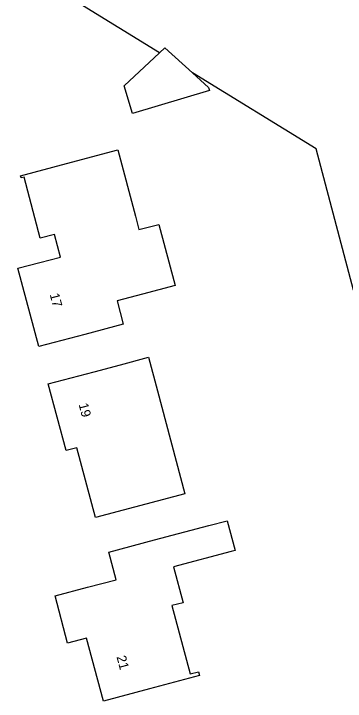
# Model space of a CAD drawing. Extents: x 162157 to 163165, y 378998 to 380775.
# Drawn here: x 162635.7 to 162670.5, y 380607.6 to 380679.9 of the extents above; entities that cross this region are included whole.
import ezdxf

# ---------------------------------------------------------------- set-up
doc = ezdxf.new("R2010")
doc.units = 0
for name, color, linetype in [('IMGEO_Berm_groen', 7, 'Continuous'), ('IMGEO_Gemengd_bos', 7, 'Continuous'), ('IMGEO_Pand', 7, 'Continuous'), ('IMGEO_Pand_nummerreeks', 7, 'Continuous')]:
    doc.layers.add(name, color=color, linetype=linetype)

msp = doc.modelspace()

# ---------------------------------------------------------------- linework, layer by layer
at = {"layer": 'IMGEO_Berm_groen'}
msp.add_arc((162610.535, 380570.327), 42.385, 51.06189, 64.46568, dxfattribs=at)
at = {"layer": 'IMGEO_Gemengd_bos'}
for points in [[(162651.018, 380675.815), (162622.41, 380693.42)], [(162686.842, 380455.383), (162698.747, 380463.798), (162717.329, 380476.675), (162717.214, 380477.109), (162722.756, 380480.815), (162721.635, 380488.635), (162709.746, 380529.126), (162706.597, 380543.52), (162702.968, 380557.567), (162695.09, 380585.37), (162687.837, 380613.552), (162683.878, 380612.514), (162673.502, 380651.377), (162671.402, 380650.811), (162667.467, 380665.693), (162654.457, 380673.698)]]:
    msp.add_lwpolyline(points, dxfattribs=at)
at = {"layer": 'IMGEO_Pand'}
for points in [[(162654.457, 380673.698), (162656.161, 380672.161), (162656.258, 380671.836), (162648.157, 380669.426), (162647.289, 380672.347), (162651.018, 380675.815)], [(162651.018, 380675.815), (162651.557, 380676.316), (162654.457, 380673.698)], [(162638.303, 380644.893), (162636.116, 380653.142), (162638.41, 380653.75), (162640.591, 380654.31), (162639.959, 380656.696), (162638.476, 380656.304), (162636.771, 380662.734), (162636.462, 380662.652), (162636.403, 380662.875), (162641.237, 380664.156), (162646.619, 380665.583), (162648.468, 380658.606), (162648.843, 380657.193), (162650.93, 380657.746), (162652.635, 380651.314), (162649.202, 380650.403), (162646.541, 380649.697), (162647.19, 380647.249), (162643.137, 380646.175), (162638.303, 380644.893)], [(162650.798, 380640.219), (162653.67, 380629.387), (162644.271, 380626.897), (162642.326, 380634.238), (162641.179, 380633.933), (162639.315, 380640.962), (162644.148, 380642.244), (162646.914, 380642.977), (162649.86, 380643.758), (162650.798, 380640.219)], [(162652.485, 380621.704), (162653.484, 380617.932), (162652.31, 380617.621), (162654.216, 380610.43), (162655.119, 380610.669), (162655.226, 380610.264), (162649.938, 380608.862), (162645.104, 380607.581), (162643.347, 380614.21), (162641.342, 380613.678), (162640.024, 380618.652), (162643.438, 380619.557), (162646.436, 380620.351), (162645.666, 380623.256), (162650.484, 380624.533), (162656.207, 380626.05), (162658.115, 380626.556), (162658.947, 380623.418), (162658.544, 380623.311), (162652.485, 380621.704)]]:
    msp.add_lwpolyline(points, dxfattribs=at)

# ---------------------------------------------------------------- texts
at = {"layer": 'IMGEO_Pand_nummerreeks'}
for s, rotation, p in [('17', 284.85086, (162639.457, 380650.374)), ('19', 284.85086, (162642.494, 380638.804)), ('21', 284.84477, (162646.479, 380612.23))]:
    msp.add_text(s, height=1, rotation=rotation, dxfattribs=at).set_placement(p)

doc.saveas('drawing.dxf')
